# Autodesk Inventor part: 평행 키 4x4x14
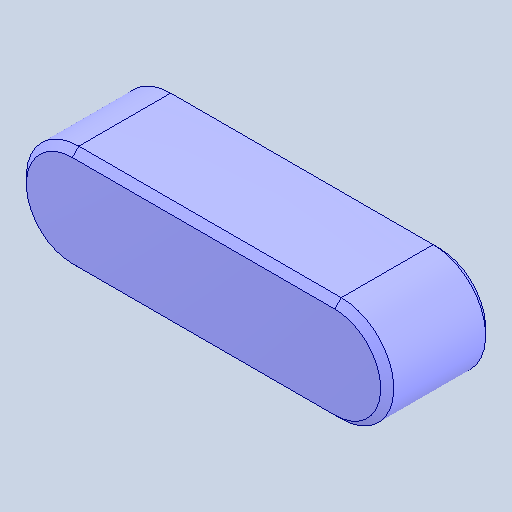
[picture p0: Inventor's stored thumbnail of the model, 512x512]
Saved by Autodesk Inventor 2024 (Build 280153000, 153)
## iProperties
Created: 2026-07
Part Number: 평행 키 4x4x14
Material: 강철, 연강
Document SubType Name: Modeling
Designer: com
Density: 7.86 g/cm^3
Appearance: 기본값
Author: jhkim
Revision Number: 1
Sending System: Autodesk Inventor 2027
Preprocessor: ST-DEVELOPER v20.1
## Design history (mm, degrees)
node "평행 키 4x4x141"
node "솔리드2"
node "솔리드1"
